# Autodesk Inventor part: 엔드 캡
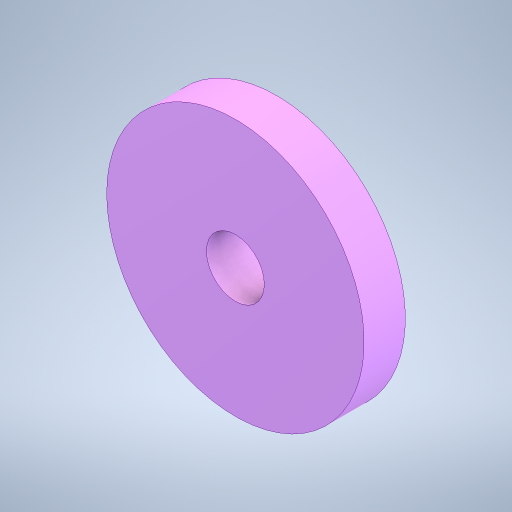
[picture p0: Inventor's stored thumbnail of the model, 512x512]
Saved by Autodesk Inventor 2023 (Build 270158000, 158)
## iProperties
Created: 2026-07
Part Number: 엔드 캡
Material: 강철, 연강
Document SubType Name: Modeling
Designer: home
Density: 7.85 g/cm^3
Appearance: 기본값
Author: jhkim
Sending System: Autodesk Inventor 2027
Preprocessor: ST-DEVELOPER v20.1
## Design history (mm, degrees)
feature "솔리드1"
node "솔리드2"
